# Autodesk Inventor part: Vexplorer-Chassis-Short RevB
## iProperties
Created: 2007-10
Part Number: Vexplorer-Chassis-Short RevB
Document SubType Name: Modeling
Material: Aluminum-6061-AHC
Density: 2.71 g/cm^3
